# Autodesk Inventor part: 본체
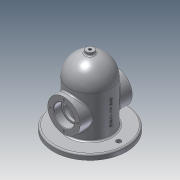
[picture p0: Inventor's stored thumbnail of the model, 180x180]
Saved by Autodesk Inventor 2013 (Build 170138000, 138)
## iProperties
Created: 2019-11
Part Number: 본체
Material: 알루미늄 6061
Document SubType Name: Modeling
Designer: user
Mass: 1110.22 g
Surface Area: 883.263 cm^2
Volume: 409.674 cm^3
Density: 2.71 g/cm^3
Author: user
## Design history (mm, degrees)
sketch "스케치1"
  geometry: L1 (0, 0)-(0, 130); L2 (0, 0)-(-40, 0); L3 (-40, 0)-(-40, 90); L4 (0, 0)-(0, 90); A1 r 40 centre (0, 90) between (0, 130) and (-40, 90)
  constraints: 8 end point, 2 perpendicular, 2 point on circle, 1 centre point, 1 coincident, 1 point on line, 1 vertical
  dimensions: "d10" = 130 distance of L1.start L1.end; "d11" = 40 distance of L1.start L2.end; "d12" = 90 distance of L3.end L2.end
revolve "회전1" sketch "스케치1" stored, may be unused: angle "d15" = 90 deg
feature "쉘1" dims "d16" = 10
sketch "스케치2"
  geometry: C1 r 40 at (0, 0) reference; C2 r 70 at (0, 0)
  constraints: 1 centre point, 1 coincident
  dimensions: "d17" = 140 diameter of C2
extrude "돌출1" join sketch "스케치2" distance "d18" = 10; taper "d19" = 0 deg
node "작업 평면1"
sketch "스케치3"
  geometry: L1 (0, 0)-(0, 50); C1 r 31 at (0, 50)
  constraints: 2 end point, 1 centre point, 1 coincident, 1 vertical
  dimensions: "d21" = 50 distance of L1.start L1.end; "d22" = 62 diameter of C1
extrude "돌출2" join sketch "스케치3" stored distance "d23" = 10; taper "d24" = 0 deg
sketch "스케치4"
  geometry: L1 (0, 0)-(0, 26); C1 r 31 at (0, 0) reference; 2 further points
  constraints: 2 end point, 1 coincident, 1 vertical
  dimensions: "d25" = 26 distance of L1.start L1.end
hole "구멍1" sketch "스케치4" at (0, 26) diameter "d26" = 3.242; stored, may be unused: countersink angle "d30" = 90 deg, drill point angle "d32" = 118 deg; dims "d27" = 8, "d28" = 4, "d29" = 2, "d31" = 10
sketch "스케치5"
  geometry: C1 r 31 at (0, 0) reference; C2 r 20 at (0, 0); 1 further point
  constraints: 1 centre point, 1 coincident
  dimensions: "d36" = 40 diameter of C2
extrude "돌출3" cut sketch "스케치5" distance "d37" = 15; taper "d38" = 0 deg
sketch "스케치6"
  geometry: C1 r 20 at (0, 0) reference; C2 r 16.5 at (0, 0); 1 further point
  constraints: 1 centre point, 1 coincident
  dimensions: "d39" = 33 diameter of C2
extrude "돌출4" cut sketch "스케치6" stored distance "d40" = 15; taper "d41" = 0 deg
node "작업 평면2"
sketch "스케치8"
  geometry: C1 r 7.5 at (0, 0); 1 further point
  constraints: 1 centre point, 1 coincident
  dimensions: "d43" = 15 diameter of C1
extrude "돌출5" join sketch "스케치8" stored distance "d44" = 15; taper "d45" = 0 deg
sketch "스케치9"
  geometry: C1 r 7.5 at (0, 0) reference; 1 further point
  constraints: 1 coincident
hole "구멍2" sketch "스케치9" at (0, 0) diameter "d46" = 5.188; stored, may be unused: countersink angle "d50" = 90 deg, drill point angle "d52" = 118 deg; dims "d47" = 8, "d48" = 4, "d49" = 2, "d51" = 10
sketch "스케치10"
  geometry: L1 (0, 0)-(55, 0); C1 r 70 at (0, 0) reference; C2 r 4.5 at (55, 0)
  constraints: 2 end point, 1 centre point, 1 coincident, 1 horizontal
  dimensions: "d53" = 55 distance of L1.start L1.end; "d54" = 9 diameter of C2
extrude "돌출6" cut sketch "스케치10" stored distance "d55" = 15; taper "d56" = 0 deg
chamfer "모따기1" distance "d60" = 1; stored, may be unused: second distance "d61" = 2, angle "d62" = 45 deg
fillet "모깎기1" dims "d63" = 0.3
fillet "모깎기2" dims "d64" = 3
node "작업 평면3"
sketch "스케치11"
  geometry: L1 (0, -70)-(0, 70) reference; 3 further points
  constraints: 1 horizontal alignment, 1 midpoint, 1 other
  dimensions: "d66" = 50 distance from line of L1 point (50, 0)
feature "엠보싱1" sketch "스케치11" dims "d10" = 130, "d11" = 40, "d12" = 90, "d67" = 0.5, "d68" = 0
node "솔리드1"
pattern_circular "원형 패턴1" dims angle "d34" = 360 deg
mirror "대칭1"
pattern_circular "원형 패턴2" dims angle "d58" = 360 deg
other parameters: "d42" = -135
